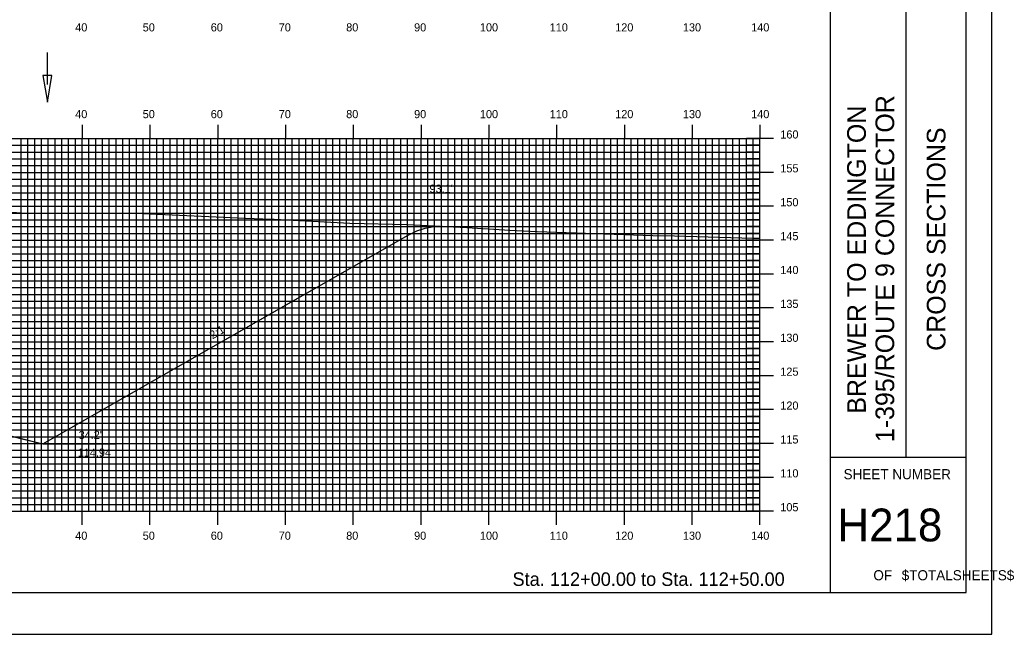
# Model space of a CAD drawing. Extents: x 1770055 to 1770398, y 442591 to 442811.
# Drawn here: x 1770251.3 to 1770398, y 442590.5 to 442681.2 of the extents above; entities that cross this region are included whole.
import ezdxf

# ---------------------------------------------------------------- set-up
doc = ezdxf.new("R2010")
doc.units = 0
for name, color, linetype in [('ANNOTATION', 7, 'Continuous'), ('BORDER', 7, 'Continuous'), ('D_Drainage_Ditch_Line', 7, 'Continuous'), ('D_Roadway_Centerline', 7, 'Continuous'), ('D_Roadway_SlopeLines', 7, 'Continuous'), ('D_Text_Standard', 7, 'Continuous'), ('H_V ANNOTATION', 7, 'Continuous'), ('MAJOR', 7, 'Continuous'), ('MINOR', 7, 'Continuous'), ('PDRAIN', 7, 'Continuous'), ('PLOT BOUNDARY', 7, 'Continuous'), ('S_Roadway_Centerline', 7, 'Continuous')]:
    doc.layers.add(name, color=color, linetype=linetype)

msp = doc.modelspace()

# ---------------------------------------------------------------- linework, layer by layer
at = {"layer": 'BORDER'}
for p, q in [((1770370.93, 442596.67), (1770370.93, 442806.67)), ((1770382.11, 442616.67), (1770382.11, 442686.67)), ((1770370.93, 442616.67), (1770390.93, 442616.67))]:
    msp.add_line(p, q, dxfattribs=at)
msp.add_lwpolyline([(1770070.93, 442596.67), (1770390.93, 442596.67), (1770390.93, 442806.67), (1770070.93, 442806.67)], close=True, dxfattribs=at)
at = {"layer": 'D_Drainage_Ditch_Line'}
msp.add_line((1770255.39, 442671.66), (1770255.39, 442676.36), dxfattribs=at)
msp.add_lwpolyline([(1770256.05, 442672.97), (1770254.73, 442672.97), (1770255.39, 442669.03)], close=True, dxfattribs=at)
at = {"layer": 'D_Roadway_Centerline'}
msp.add_lwpolyline([(1770250.7, 442619.6), (1770253.91, 442618.8), (1770254.7, 442618.6), (1770294.41, 442641.29), (1770308.64, 442649.42), (1770309.89, 442650.04), (1770310.54, 442650.26), (1770311.14, 442650.46), (1770312.39, 442650.69), (1770313.64, 442650.73)], dxfattribs=at)
at = {"layer": 'D_Roadway_SlopeLines'}
for points in [[(1770254.7, 442618.6), (1770308.64, 442649.42), (1770309.89, 442650.04), (1770311.14, 442650.46), (1770312.39, 442650.69), (1770313.64, 442650.73)], [(1770240.53, 442622.15), (1770254.7, 442618.6)]]:
    msp.add_lwpolyline(points, dxfattribs=at)
at = {"layer": 'MAJOR'}
for p, q in [((1770260.53, 442665.67), (1770260.53, 442663.67)), ((1770270.53, 442665.67), (1770270.53, 442663.67)), ((1770280.53, 442665.67), (1770280.53, 442663.67)), ((1770290.53, 442665.67), (1770290.53, 442663.67)), ((1770300.53, 442665.67), (1770300.53, 442663.67)), ((1770310.53, 442665.67), (1770310.53, 442663.67)), ((1770320.53, 442665.67), (1770320.53, 442663.67)), ((1770330.53, 442665.67), (1770330.53, 442663.67)), ((1770340.53, 442665.67), (1770340.53, 442663.67)), ((1770350.53, 442665.67), (1770350.53, 442663.67)), ((1770360.53, 442665.67), (1770360.53, 442663.67)), ((1770080.53, 442663.67), (1770360.53, 442663.67)), ((1770080.53, 442663.67), (1770360.53, 442663.67)), ((1770260.53, 442608.67), (1770260.53, 442663.67)), ((1770270.53, 442608.67), (1770270.53, 442663.67)), ((1770280.53, 442608.67), (1770280.53, 442663.67)), ((1770290.53, 442608.67), (1770290.53, 442663.67)), ((1770300.53, 442608.67), (1770300.53, 442663.67)), ((1770310.53, 442608.67), (1770310.53, 442663.67)), ((1770320.53, 442608.67), (1770320.53, 442663.67)), ((1770330.53, 442608.67), (1770330.53, 442663.67)), ((1770340.53, 442608.67), (1770340.53, 442663.67)), ((1770350.53, 442608.67), (1770350.53, 442663.67)), ((1770362.53, 442663.67), (1770358.52, 442663.67)), ((1770360.53, 442608.67), (1770360.53, 442663.67)), ((1770360.53, 442608.67), (1770360.53, 442663.67)), ((1770080.53, 442658.67), (1770360.53, 442658.67)), ((1770362.53, 442658.67), (1770358.52, 442658.67)), ((1770080.53, 442653.67), (1770360.53, 442653.67)), ((1770362.53, 442653.67), (1770358.52, 442653.67)), ((1770080.53, 442648.67), (1770360.53, 442648.67)), ((1770362.53, 442648.67), (1770358.52, 442648.67)), ((1770080.53, 442643.67), (1770360.53, 442643.67)), ((1770362.53, 442643.67), (1770358.52, 442643.67)), ((1770080.53, 442638.67), (1770360.53, 442638.67)), ((1770362.53, 442638.67), (1770358.52, 442638.67)), ((1770080.53, 442633.67), (1770360.53, 442633.67)), ((1770362.53, 442633.67), (1770358.52, 442633.67)), ((1770080.53, 442628.67), (1770360.53, 442628.67)), ((1770362.53, 442628.67), (1770358.52, 442628.67)), ((1770080.53, 442623.67), (1770360.53, 442623.67)), ((1770362.53, 442623.67), (1770358.52, 442623.67)), ((1770080.53, 442618.67), (1770360.53, 442618.67)), ((1770362.53, 442618.67), (1770358.52, 442618.67)), ((1770080.53, 442613.67), (1770360.53, 442613.67)), ((1770362.53, 442613.67), (1770358.52, 442613.67)), ((1770080.53, 442608.67), (1770360.53, 442608.67)), ((1770080.53, 442608.67), (1770360.53, 442608.67)), ((1770260.53, 442606.66), (1770260.53, 442608.67)), ((1770270.53, 442606.66), (1770270.53, 442608.67)), ((1770280.53, 442606.66), (1770280.53, 442608.67)), ((1770290.53, 442606.66), (1770290.53, 442608.67)), ((1770300.53, 442606.66), (1770300.53, 442608.67)), ((1770310.53, 442606.66), (1770310.53, 442608.67)), ((1770320.53, 442606.66), (1770320.53, 442608.67)), ((1770330.53, 442606.66), (1770330.53, 442608.67)), ((1770340.53, 442606.66), (1770340.53, 442608.67)), ((1770350.53, 442606.66), (1770350.53, 442608.67)), ((1770362.53, 442608.67), (1770358.52, 442608.67)), ((1770360.53, 442606.66), (1770360.53, 442608.67))]:
    msp.add_line(p, q, dxfattribs=at)
at = {"layer": 'MINOR'}
for p, q in [((1770080.53, 442662.67), (1770360.53, 442662.67)), ((1770251.53, 442608.67), (1770251.53, 442663.67)), ((1770252.53, 442608.67), (1770252.53, 442663.67)), ((1770253.53, 442608.67), (1770253.53, 442663.67)), ((1770254.53, 442608.67), (1770254.53, 442663.67)), ((1770255.53, 442608.67), (1770255.53, 442663.67)), ((1770256.53, 442608.67), (1770256.53, 442663.67)), ((1770257.53, 442608.67), (1770257.53, 442663.67)), ((1770258.53, 442608.67), (1770258.53, 442663.67)), ((1770259.53, 442608.67), (1770259.53, 442663.67)), ((1770261.53, 442608.67), (1770261.53, 442663.67)), ((1770262.53, 442608.67), (1770262.53, 442663.67)), ((1770263.53, 442608.67), (1770263.53, 442663.67)), ((1770264.53, 442608.67), (1770264.53, 442663.67)), ((1770265.53, 442608.67), (1770265.53, 442663.67)), ((1770266.53, 442608.67), (1770266.53, 442663.67)), ((1770267.53, 442608.67), (1770267.53, 442663.67)), ((1770268.53, 442608.67), (1770268.53, 442663.67)), ((1770269.53, 442608.67), (1770269.53, 442663.67)), ((1770271.53, 442608.67), (1770271.53, 442663.67)), ((1770272.53, 442608.67), (1770272.53, 442663.67)), ((1770273.53, 442608.67), (1770273.53, 442663.67)), ((1770274.53, 442608.67), (1770274.53, 442663.67)), ((1770275.53, 442608.67), (1770275.53, 442663.67)), ((1770276.53, 442608.67), (1770276.53, 442663.67)), ((1770277.53, 442608.67), (1770277.53, 442663.67)), ((1770278.53, 442608.67), (1770278.53, 442663.67)), ((1770279.53, 442608.67), (1770279.53, 442663.67)), ((1770281.53, 442608.67), (1770281.53, 442663.67)), ((1770282.53, 442608.67), (1770282.53, 442663.67)), ((1770283.53, 442608.67), (1770283.53, 442663.67)), ((1770284.53, 442608.67), (1770284.53, 442663.67)), ((1770285.53, 442608.67), (1770285.53, 442663.67)), ((1770286.53, 442608.67), (1770286.53, 442663.67)), ((1770287.53, 442608.67), (1770287.53, 442663.67)), ((1770288.53, 442608.67), (1770288.53, 442663.67)), ((1770289.53, 442608.67), (1770289.53, 442663.67)), ((1770291.53, 442608.67), (1770291.53, 442663.67)), ((1770292.53, 442608.67), (1770292.53, 442663.67)), ((1770293.53, 442608.67), (1770293.53, 442663.67)), ((1770294.53, 442608.67), (1770294.53, 442663.67)), ((1770295.53, 442608.67), (1770295.53, 442663.67)), ((1770296.53, 442608.67), (1770296.53, 442663.67)), ((1770297.53, 442608.67), (1770297.53, 442663.67)), ((1770298.53, 442608.67), (1770298.53, 442663.67)), ((1770299.53, 442608.67), (1770299.53, 442663.67)), ((1770301.53, 442608.67), (1770301.53, 442663.67)), ((1770302.53, 442608.67), (1770302.53, 442663.67)), ((1770303.53, 442608.67), (1770303.53, 442663.67)), ((1770304.53, 442608.67), (1770304.53, 442663.67)), ((1770305.53, 442608.67), (1770305.53, 442663.67)), ((1770306.53, 442608.67), (1770306.53, 442663.67)), ((1770307.53, 442608.67), (1770307.53, 442663.67)), ((1770308.53, 442608.67), (1770308.53, 442663.67)), ((1770309.53, 442608.67), (1770309.53, 442663.67)), ((1770311.53, 442608.67), (1770311.53, 442663.67)), ((1770312.53, 442608.67), (1770312.53, 442663.67)), ((1770313.53, 442608.67), (1770313.53, 442663.67)), ((1770314.53, 442608.67), (1770314.53, 442663.67)), ((1770315.53, 442608.67), (1770315.53, 442663.67)), ((1770316.53, 442608.67), (1770316.53, 442663.67)), ((1770317.53, 442608.67), (1770317.53, 442663.67)), ((1770318.53, 442608.67), (1770318.53, 442663.67)), ((1770319.53, 442608.67), (1770319.53, 442663.67)), ((1770321.53, 442608.67), (1770321.53, 442663.67)), ((1770322.53, 442608.67), (1770322.53, 442663.67)), ((1770323.53, 442608.67), (1770323.53, 442663.67)), ((1770324.53, 442608.67), (1770324.53, 442663.67)), ((1770325.53, 442608.67), (1770325.53, 442663.67)), ((1770326.53, 442608.67), (1770326.53, 442663.67)), ((1770327.53, 442608.67), (1770327.53, 442663.67)), ((1770328.53, 442608.67), (1770328.53, 442663.67)), ((1770329.53, 442608.67), (1770329.53, 442663.67)), ((1770331.53, 442608.67), (1770331.53, 442663.67)), ((1770332.53, 442608.67), (1770332.53, 442663.67)), ((1770333.53, 442608.67), (1770333.53, 442663.67)), ((1770334.53, 442608.67), (1770334.53, 442663.67)), ((1770335.53, 442608.67), (1770335.53, 442663.67)), ((1770336.53, 442608.67), (1770336.53, 442663.67)), ((1770337.53, 442608.67), (1770337.53, 442663.67)), ((1770338.53, 442608.67), (1770338.53, 442663.67)), ((1770339.53, 442608.67), (1770339.53, 442663.67)), ((1770341.53, 442608.67), (1770341.53, 442663.67)), ((1770342.53, 442608.67), (1770342.53, 442663.67)), ((1770343.53, 442608.67), (1770343.53, 442663.67)), ((1770344.53, 442608.67), (1770344.53, 442663.67)), ((1770345.53, 442608.67), (1770345.53, 442663.67)), ((1770346.53, 442608.67), (1770346.53, 442663.67)), ((1770347.53, 442608.67), (1770347.53, 442663.67)), ((1770348.53, 442608.67), (1770348.53, 442663.67)), ((1770349.53, 442608.67), (1770349.53, 442663.67)), ((1770351.53, 442608.67), (1770351.53, 442663.67)), ((1770352.53, 442608.67), (1770352.53, 442663.67)), ((1770353.53, 442608.67), (1770353.53, 442663.67)), ((1770354.53, 442608.67), (1770354.53, 442663.67)), ((1770355.53, 442608.67), (1770355.53, 442663.67)), ((1770356.53, 442608.67), (1770356.53, 442663.67)), ((1770357.53, 442608.67), (1770357.53, 442663.67)), ((1770360.53, 442662.67), (1770358.52, 442662.67)), ((1770358.53, 442608.67), (1770358.53, 442663.67)), ((1770359.53, 442608.67), (1770359.53, 442663.67)), ((1770080.53, 442661.67), (1770360.53, 442661.67)), ((1770360.53, 442661.67), (1770358.52, 442661.67)), ((1770080.53, 442660.67), (1770360.53, 442660.67)), ((1770080.53, 442659.67), (1770360.53, 442659.67)), ((1770360.53, 442660.67), (1770358.52, 442660.67)), ((1770360.53, 442659.67), (1770358.52, 442659.67)), ((1770080.53, 442657.67), (1770360.53, 442657.67)), ((1770360.53, 442657.67), (1770358.52, 442657.67)), ((1770080.53, 442656.67), (1770360.53, 442656.67)), ((1770080.53, 442655.67), (1770360.53, 442655.67)), ((1770360.53, 442656.67), (1770358.52, 442656.67)), ((1770360.53, 442655.67), (1770358.52, 442655.67)), ((1770080.53, 442654.67), (1770360.53, 442654.67)), ((1770360.53, 442654.67), (1770358.52, 442654.67)), ((1770080.53, 442652.67), (1770360.53, 442652.67)), ((1770360.53, 442652.67), (1770358.52, 442652.67)), ((1770080.53, 442651.67), (1770360.53, 442651.67)), ((1770360.53, 442651.67), (1770358.52, 442651.67)), ((1770080.53, 442650.67), (1770360.53, 442650.67)), ((1770080.53, 442649.67), (1770360.53, 442649.67)), ((1770360.53, 442650.67), (1770358.52, 442650.67)), ((1770360.53, 442649.67), (1770358.52, 442649.67)), ((1770080.53, 442647.67), (1770360.53, 442647.67)), ((1770080.53, 442646.67), (1770360.53, 442646.67)), ((1770360.53, 442647.67), (1770358.52, 442647.67)), ((1770360.53, 442646.67), (1770358.52, 442646.67)), ((1770080.53, 442645.67), (1770360.53, 442645.67)), ((1770360.53, 442645.67), (1770358.52, 442645.67)), ((1770080.53, 442644.67), (1770360.53, 442644.67)), ((1770360.53, 442644.67), (1770358.52, 442644.67)), ((1770080.53, 442642.67), (1770360.53, 442642.67)), ((1770360.53, 442642.67), (1770358.52, 442642.67)), ((1770080.53, 442641.67), (1770360.53, 442641.67)), ((1770080.53, 442640.67), (1770360.53, 442640.67)), ((1770360.53, 442641.67), (1770358.52, 442641.67)), ((1770360.53, 442640.67), (1770358.52, 442640.67)), ((1770080.53, 442639.67), (1770360.53, 442639.67)), ((1770360.53, 442639.67), (1770358.52, 442639.67)), ((1770080.53, 442637.67), (1770360.53, 442637.67)), ((1770360.53, 442637.67), (1770358.52, 442637.67)), ((1770080.53, 442636.67), (1770360.53, 442636.67)), ((1770360.53, 442636.67), (1770358.52, 442636.67)), ((1770080.53, 442635.67), (1770360.53, 442635.67)), ((1770360.53, 442635.67), (1770358.52, 442635.67)), ((1770080.53, 442634.67), (1770360.53, 442634.67)), ((1770360.53, 442634.67), (1770358.52, 442634.67)), ((1770080.53, 442632.67), (1770360.53, 442632.67)), ((1770360.53, 442632.67), (1770358.52, 442632.67)), ((1770080.53, 442631.67), (1770360.53, 442631.67)), ((1770080.53, 442630.67), (1770360.53, 442630.67)), ((1770360.53, 442631.67), (1770358.52, 442631.67)), ((1770360.53, 442630.67), (1770358.52, 442630.67)), ((1770080.53, 442629.67), (1770360.53, 442629.67)), ((1770360.53, 442629.67), (1770358.52, 442629.67)), ((1770080.53, 442627.67), (1770360.53, 442627.67)), ((1770360.53, 442627.67), (1770358.52, 442627.67)), ((1770080.53, 442626.67), (1770360.53, 442626.67)), ((1770360.53, 442626.67), (1770358.52, 442626.67)), ((1770080.53, 442625.67), (1770360.53, 442625.67)), ((1770080.53, 442624.67), (1770360.53, 442624.67)), ((1770360.53, 442625.67), (1770358.52, 442625.67)), ((1770360.53, 442624.67), (1770358.52, 442624.67)), ((1770080.53, 442622.67), (1770360.53, 442622.67)), ((1770080.53, 442621.67), (1770360.53, 442621.67)), ((1770360.53, 442622.67), (1770358.52, 442622.67)), ((1770360.53, 442621.67), (1770358.52, 442621.67)), ((1770080.53, 442620.67), (1770360.53, 442620.67)), ((1770360.53, 442620.67), (1770358.52, 442620.67)), ((1770080.53, 442619.67), (1770360.53, 442619.67)), ((1770360.53, 442619.67), (1770358.52, 442619.67)), ((1770080.53, 442617.67), (1770360.53, 442617.67)), ((1770360.53, 442617.67), (1770358.52, 442617.67)), ((1770080.53, 442616.67), (1770360.53, 442616.67)), ((1770080.53, 442615.67), (1770360.53, 442615.67)), ((1770360.53, 442616.67), (1770358.52, 442616.67)), ((1770360.53, 442615.67), (1770358.52, 442615.67)), ((1770080.53, 442614.67), (1770360.53, 442614.67)), ((1770360.53, 442614.67), (1770358.52, 442614.67)), ((1770080.53, 442612.67), (1770360.53, 442612.67)), ((1770080.53, 442611.67), (1770360.53, 442611.67)), ((1770360.53, 442612.67), (1770358.52, 442612.67)), ((1770360.53, 442611.67), (1770358.52, 442611.67)), ((1770080.53, 442610.67), (1770360.53, 442610.67)), ((1770360.53, 442610.67), (1770358.52, 442610.67)), ((1770080.53, 442609.67), (1770360.53, 442609.67)), ((1770360.53, 442609.67), (1770358.52, 442609.67))]:
    msp.add_line(p, q, dxfattribs=at)
at = {"layer": 'PDRAIN'}
msp.add_line((1770254.7, 442618.6), (1770265.47, 442618.6), dxfattribs=at)
at = {"layer": 'PLOT BOUNDARY'}
msp.add_lwpolyline([(1770054.74, 442590.55), (1770394.74, 442590.55), (1770394.74, 442810.55), (1770054.74, 442810.55)], close=True, dxfattribs=at)
at = {"layer": 'S_Roadway_Centerline'}
msp.add_lwpolyline([(1770247.85, 442652.97), (1770251.57, 442652.68), (1770252.31, 442652.66), (1770253.46, 442652.66), (1770269.47, 442652.59), (1770284.61, 442651.94), (1770287.16, 442651.8), (1770288.83, 442651.75), (1770300.04, 442651.19), (1770308.45, 442650.98), (1770317.27, 442650.54), (1770323.61, 442650.14), (1770327.64, 442649.96), (1770344.7, 442649.38), (1770347.9, 442649.3), (1770359.53, 442648.97), (1770360.53, 442648.95)], dxfattribs=at)

# ---------------------------------------------------------------- texts
at = {"layer": 'ANNOTATION'}
msp.add_text('2:1', height=1.2, rotation=29.7448, dxfattribs=at).set_placement((1770279.75, 442634.02))
for s, p in [("34.2'", (1770260.01, 442619.33)), ('114.94', (1770259.87, 442616.73))]:
    msp.add_text(s, height=1.2, dxfattribs=at).set_placement(p)
at = {"layer": 'BORDER'}
for s, p in [('1-395/ROUTE 9 CONNECTOR', (1770380.33, 442618.87)), ('BREWER TO EDDINGTON', (1770376.15, 442623.07)), ('CROSS SECTIONS', (1770387.9, 442632.34))]:
    msp.add_text(s, height=2.7557, rotation=90, dxfattribs=at).set_placement(p)
for s, height, p in [('SHEET NUMBER', 1.4905, (1770372.86, 442613.4)), ('H218', 4.839, (1770371.96, 442604.23)), ('OF', 1.491, (1770377.26, 442598.49)), ('$TOTALSHEETS$', 1.4905, (1770381.44, 442598.49))]:
    msp.add_text(s, height=height, dxfattribs=at).set_placement(p)
at = {"layer": 'D_Text_Standard'}
msp.add_text("93.1'", height=1.2, dxfattribs=at).set_placement((1770311.77, 442655.67))
at = {"layer": 'H_V ANNOTATION'}
for s, height, p in [('40', 1.2, (1770259.5, 442679.47)), ('50', 1.2, (1770269.46, 442679.47)), ('60', 1.2, (1770279.5, 442679.47)), ('70', 1.2, (1770289.53, 442679.47)), ('80', 1.2, (1770299.48, 442679.47)), ('90', 1.2, (1770309.5, 442679.47)), ('100', 1.2, (1770319.21, 442679.47)), ('110', 1.2, (1770329.51, 442679.47)), ('120', 1.2, (1770339.17, 442679.47)), ('130', 1.2, (1770349.16, 442679.47)), ('140', 1.2, (1770359.23, 442679.47)), ('40', 1.2, (1770259.5, 442666.67)), ('50', 1.2, (1770269.46, 442666.67)), ('60', 1.2, (1770279.5, 442666.67)), ('70', 1.2, (1770289.53, 442666.67)), ('80', 1.2, (1770299.48, 442666.67)), ('90', 1.2, (1770309.5, 442666.67)), ('100', 1.2, (1770319.21, 442666.67)), ('110', 1.2, (1770329.51, 442666.67)), ('120', 1.2, (1770339.17, 442666.67)), ('130', 1.2, (1770349.16, 442666.67)), ('140', 1.2, (1770359.23, 442666.67)), ('160', 1.2, (1770363.53, 442663.67)), ('155', 1.2, (1770363.53, 442658.67)), ('150', 1.2, (1770363.53, 442653.67)), ('145', 1.2, (1770363.53, 442648.67)), ('140', 1.2, (1770363.53, 442643.67)), ('135', 1.2, (1770363.53, 442638.67)), ('130', 1.2, (1770363.53, 442633.67)), ('125', 1.2, (1770363.53, 442628.67)), ('120', 1.2, (1770363.53, 442623.67)), ('115', 1.2, (1770363.53, 442618.67)), ('110', 1.2, (1770363.53, 442613.67)), ('105', 1.2, (1770363.53, 442608.67)), ('40', 1.2, (1770259.5, 442604.47)), ('50', 1.2, (1770269.46, 442604.47)), ('60', 1.2, (1770279.5, 442604.47)), ('70', 1.2, (1770289.53, 442604.47)), ('80', 1.2, (1770299.48, 442604.47)), ('90', 1.2, (1770309.5, 442604.47)), ('100', 1.2, (1770319.21, 442604.47)), ('110', 1.2, (1770329.51, 442604.47)), ('120', 1.2, (1770339.17, 442604.47)), ('130', 1.2, (1770349.16, 442604.47)), ('140', 1.2, (1770359.23, 442604.47)), ('Sta. 112+00.00 to Sta. 112+50.00', 2.0004, (1770324.02, 442597.66))]:
    msp.add_text(s, height=height, dxfattribs=at).set_placement(p)

doc.saveas('drawing.dxf')
